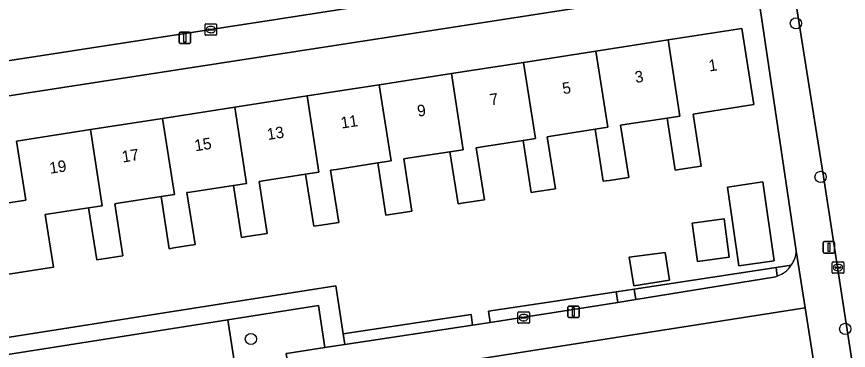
# Model space of a CAD drawing. Extents: x 160077 to 160948, y 386481 to 387498.
# Drawn here: x 160283.4 to 160355.9, y 387324.3 to 387353.4 of the extents above; entities that cross this region are included whole.
import ezdxf

# ---------------------------------------------------------------- set-up
doc = ezdxf.new("R2010")
doc.units = 0
for name, color, linetype in [('IMGEO_Boom', 7, 'Continuous'), ('IMGEO_Erf', 7, 'Continuous'), ('IMGEO_Groenvoorziening', 7, 'Continuous'), ('IMGEO_Haag', 7, 'Continuous'), ('IMGEO_Hek', 7, 'Continuous'), ('IMGEO_Kolk', 7, 'Continuous'), ('IMGEO_Lichtmast', 7, 'Continuous'), ('IMGEO_Pand', 7, 'Continuous'), ('IMGEO_Pand_nummerreeks', 7, 'Continuous'), ('IMGEO_Rijbaan_lokaal_open', 7, 'Continuous'), ('IMGEO_Voetpad_open', 7, 'Continuous')]:
    doc.layers.add(name, color=color, linetype=linetype)

msp = doc.modelspace()

# ---------------------------------------------------------------- linework, layer by layer
at = {"layer": 'IMGEO_Boom'}
for centre in [(160351.331, 387352.8), (160353.483, 387339.399), (160355.634, 387326.139), (160303.826, 387325.258)]:
    msp.add_circle(centre, 0.489, dxfattribs=at)
at = {"layer": 'IMGEO_Erf'}
for points in [[(160345.165, 387356.158), (160277.066, 387345.597)], [(160351.371, 387332.958), (160348.215, 387354.083)], [(160280.249, 387336.766), (160284.197, 387337.379), (160283.396, 387342.532), (160289.831, 387343.531), (160296.126, 387344.509), (160302.42, 387345.486), (160308.715, 387346.464), (160315.01, 387347.441), (160321.304, 387348.418), (160327.599, 387349.396), (160333.893, 387350.373), (160340.188, 387351.351), (160346.623, 387352.35), (160347.655, 387345.706), (160342.898, 387344.967), (160342.377, 387344.886), (160343.083, 387340.342), (160341.343, 387340.072), (160340.809, 387339.989), (160340.103, 387344.533), (160336.593, 387343.988), (160336.053, 387343.904), (160336.759, 387339.36), (160335.068, 387339.098), (160334.545, 387339.017), (160333.839, 387343.561), (160330.178, 387342.992), (160329.656, 387342.911), (160330.362, 387338.367), (160328.784, 387338.122), (160328.257, 387338.04), (160327.551, 387342.584), (160323.984, 387342.03), (160323.473, 387341.951), (160324.179, 387337.408), (160322.374, 387337.127), (160321.883, 387337.051), (160321.177, 387341.594), (160317.677, 387341.051), (160317.148, 387340.969), (160317.854, 387336.425), (160316.173, 387336.164), (160315.598, 387336.075), (160314.892, 387340.618), (160311.274, 387340.056), (160310.771, 387339.978), (160311.477, 387335.434), (160309.752, 387335.166), (160309.301, 387335.096), (160308.596, 387339.638), (160304.902, 387339.067), (160304.543, 387339.011), (160305.249, 387334.468), (160303.459, 387334.19), (160303.004, 387334.119), (160302.299, 387338.662), (160298.519, 387338.076), (160298.249, 387338.034), (160298.955, 387333.49), (160297.097, 387333.202), (160296.705, 387333.141), (160295.999, 387337.684), (160292.25, 387337.102), (160291.955, 387337.056), (160292.661, 387332.513), (160290.783, 387332.221), (160290.383, 387332.159), (160289.677, 387336.703), (160285.887, 387336.114), (160286.6, 387331.526), (160281.193, 387330.687)], [(160274.772, 387342.45), (160277.587, 387324.592), (160311.213, 387329.893), (160311.864, 387325.704), (160323.038, 387327.4), (160323.143, 387326.454), (160324.679, 387326.687), (160324.528, 387327.681), (160330.176, 387328.538), (160335.674, 387329.373), (160337.241, 387329.611), (160349.608, 387331.488), (160350.932, 387331.689)], [(160355.751, 387304.187), (160355.398, 387307.291), (160352.153, 387327.971), (160310.416, 387321.441), (160314.017, 387298.456), (160314.061, 387298.234), (160314.124, 387298.017), (160314.206, 387297.806), (160314.307, 387297.603), (160314.426, 387297.41), (160314.561, 387297.229), (160314.712, 387297.06), (160314.749, 387297.023), (160327.622, 387298.956), (160328.806, 387299.134), (160329.073, 387299.174), (160339.014, 387300.655), (160341.387, 387301.023), (160341.842, 387301.093), (160341.795, 387301.407), (160354.477, 387303.432)], [(160305.938, 387282.835), (160305.245, 387287.39), (160307.739, 387287.769), (160307.211, 387291.392), (160304.718, 387291.013), (160304.144, 387294.781), (160303.444, 387299.383), (160305.938, 387299.762), (160305.449, 387303.021), (160302.956, 387302.642), (160302.335, 387306.725), (160301.682, 387311.012), (160304.176, 387311.391), (160304.04, 387312.282), (160303.781, 387313.992), (160303.628, 387314.996), (160301.133, 387314.617), (160300.516, 387318.668), (160299.861, 387322.974), (160302.357, 387323.353), (160301.814, 387326.925), (160277.816, 387323.142), (160287.045, 387264.59)]]:
    msp.add_lwpolyline(points, dxfattribs=at)
for points in [[(160345.364, 387338.52), (160348.438, 387338.968), (160349.442, 387332.078), (160346.368, 387331.63)], [(160342.29, 387335.359), (160345.068, 387335.739), (160345.523, 387332.405), (160342.745, 387332.025)], [(160336.799, 387332.389), (160339.929, 387332.8), (160340.314, 387330.388), (160337.197, 387329.891)]]:
    msp.add_lwpolyline(points, close=True, dxfattribs=at)
msp.add_arc((160348.839, 387333.123), 2.537, 325.57268, 356.26205, dxfattribs=at)
at = {"layer": 'IMGEO_Groenvoorziening'}
for points in [[(160349.424, 387330.658), (160349.566, 387330.696), (160349.705, 387330.742), (160349.608, 387331.488), (160337.241, 387329.611), (160337.378, 387328.71)], [(160335.813, 387328.457), (160335.674, 387329.373), (160330.176, 387328.538), (160324.528, 387327.681), (160324.679, 387326.687)], [(160306.887, 387323.99), (160307.144, 387324.03), (160310.282, 387324.506), (160309.705, 387328.169), (160301.814, 387326.925), (160302.357, 387323.353), (160303.011, 387319.054), (160303.628, 387314.996), (160303.781, 387313.992), (160308.303, 387314.677), (160307.652, 387318.96)], [(160323.143, 387326.454), (160323.038, 387327.4), (160311.864, 387325.704), (160312.006, 387324.767)]]:
    msp.add_lwpolyline(points, close=True, dxfattribs=at)
msp.add_lwpolyline([(160350.932, 387331.689), (160349.608, 387331.488), (160349.705, 387330.742)], dxfattribs=at)
msp.add_arc((160348.846, 387333.123), 2.531, 289.83448, 325.48752, dxfattribs=at)
at = {"layer": 'IMGEO_Haag'}
for points in [[(160349.705, 387330.742), (160349.608, 387331.488), (160337.241, 387329.611), (160337.378, 387328.71), (160349.424, 387330.658), (160349.566, 387330.696)], [(160335.674, 387329.373), (160330.176, 387328.538), (160324.528, 387327.681), (160324.679, 387326.687), (160335.813, 387328.457)], [(160323.143, 387326.454), (160323.038, 387327.4), (160311.864, 387325.704), (160312.006, 387324.767)]]:
    msp.add_lwpolyline(points, close=True, dxfattribs=at)
at = {"layer": 'IMGEO_Hek'}
for points in [[(160337.241, 387329.611), (160349.608, 387331.488)], [(160330.176, 387328.538), (160335.674, 387329.373)], [(160311.864, 387325.704), (160323.038, 387327.4)]]:
    msp.add_lwpolyline(points, dxfattribs=at)
at = {"layer": 'IMGEO_Kolk'}
for p, q in [((160299.825, 387351.831), (160299.825, 387352.683)), ((160299.9, 387352.757), (160300.752, 387352.757)), ((160300.313, 387352.537), (160300.338, 387352.537)), ((160300.826, 387352.683), (160300.826, 387351.831)), ((160300.752, 387351.757), (160299.9, 387351.757)), ((160300.084, 387352.251), (160300.084, 387352.263)), ((160300.522, 387352.214), (160300.124, 387352.214)), ((160300.127, 387352.3), (160300.525, 387352.3)), ((160300.336, 387351.977), (160300.311, 387351.977)), ((160300.568, 387352.263), (160300.568, 387352.251)), ((160354.502, 387331.066), (160354.502, 387331.918)), ((160354.577, 387331.992), (160355.429, 387331.992)), ((160354.761, 387331.486), (160354.761, 387331.498)), ((160355.199, 387331.449), (160354.801, 387331.449)), ((160354.804, 387331.535), (160355.202, 387331.535)), ((160354.99, 387331.772), (160355.015, 387331.772)), ((160355.245, 387331.498), (160355.245, 387331.486)), ((160355.503, 387331.918), (160355.503, 387331.066)), ((160355.429, 387330.992), (160354.577, 387330.992)), ((160355.013, 387331.212), (160354.988, 387331.212)), ((160327.101, 387326.703), (160327.101, 387327.555)), ((160327.176, 387327.629), (160328.028, 387327.629)), ((160327.36, 387327.123), (160327.36, 387327.135)), ((160327.798, 387327.086), (160327.4, 387327.086)), ((160327.403, 387327.172), (160327.801, 387327.172)), ((160327.589, 387327.409), (160327.614, 387327.409)), ((160327.844, 387327.135), (160327.844, 387327.123)), ((160328.102, 387327.555), (160328.102, 387326.703)), ((160328.028, 387326.629), (160327.176, 387326.629)), ((160327.612, 387326.849), (160327.587, 387326.849))]:
    msp.add_line(p, q, dxfattribs=at)
for points in [[(160299.825, 387351.831), (160299.825, 387352.683)], [(160299.9, 387352.757), (160300.752, 387352.757)], [(160300.826, 387352.683), (160300.826, 387351.831)], [(160300.752, 387351.757), (160299.9, 387351.757)], [(160354.502, 387331.066), (160354.502, 387331.918)], [(160354.577, 387331.992), (160355.429, 387331.992)], [(160355.503, 387331.918), (160355.503, 387331.066)], [(160355.429, 387330.992), (160354.577, 387330.992)], [(160327.101, 387326.703), (160327.101, 387327.555)], [(160327.176, 387327.629), (160328.028, 387327.629)], [(160328.102, 387327.555), (160328.102, 387326.703)], [(160328.028, 387326.629), (160327.176, 387326.629)]]:
    msp.add_lwpolyline(points, dxfattribs=at)
for centre, radius, start, end in [((160299.902, 387352.681), 0.0765, 91.55205, 178.44795), ((160299.902, 387352.681), 0.0765, 91.55205, 178.44795), ((160300.75, 387352.681), 0.0765, 1.55205, 88.44795), ((160300.75, 387352.681), 0.0765, 1.55205, 88.44795), ((160299.902, 387351.833), 0.0765, 181.55205, 268.44795), ((160299.902, 387351.833), 0.0765, 181.55205, 268.44795), ((160300.124, 387352.26), 0.0403, 85.87752, 175.75265), ((160300.121, 387352.25), 0.0366, 178.93798, 274.71019), ((160300.525, 387352.257), 0.043, 264.86636, 352.45326), ((160300.529, 387352.262), 0.0386, 1.73085, 96.63898), ((160300.75, 387351.833), 0.0765, 271.55205, 358.44795), ((160300.75, 387351.833), 0.0765, 271.55205, 358.44795), ((160354.579, 387331.916), 0.0765, 91.55205, 178.44795), ((160354.579, 387331.916), 0.0765, 91.55205, 178.44795), ((160354.801, 387331.495), 0.0403, 85.87752, 175.75265), ((160354.798, 387331.485), 0.0366, 178.93798, 274.71019), ((160355.202, 387331.492), 0.043, 264.86636, 352.45326), ((160355.206, 387331.497), 0.0386, 1.73085, 96.63898), ((160355.427, 387331.916), 0.0765, 1.55205, 88.44795), ((160355.427, 387331.916), 0.0765, 1.55205, 88.44795), ((160354.579, 387331.068), 0.0765, 181.55205, 268.44795), ((160354.579, 387331.068), 0.0765, 181.55205, 268.44795), ((160355.427, 387331.068), 0.0765, 271.55205, 358.44795), ((160355.427, 387331.068), 0.0765, 271.55205, 358.44795), ((160327.178, 387327.553), 0.0765, 91.55205, 178.44795), ((160327.178, 387327.553), 0.0765, 91.55205, 178.44795), ((160327.4, 387327.132), 0.0403, 85.87752, 175.75265), ((160327.397, 387327.122), 0.0366, 178.93798, 274.71019), ((160327.801, 387327.129), 0.043, 264.86636, 352.45326), ((160327.805, 387327.134), 0.0386, 1.73085, 96.63898), ((160328.026, 387327.553), 0.0765, 1.55205, 88.44795), ((160328.026, 387327.553), 0.0765, 1.55205, 88.44795), ((160327.178, 387326.705), 0.0765, 181.55205, 268.44795), ((160327.178, 387326.705), 0.0765, 181.55205, 268.44795), ((160328.026, 387326.705), 0.0765, 271.55205, 358.44795), ((160328.026, 387326.705), 0.0765, 271.55205, 358.44795)]:
    msp.add_arc(centre, radius, start, end, dxfattribs=at)
for centre, major_axis, ratio, start_param, end_param in [((160300.312, 387352.257), (-0.387, 0.002), 0.722429, 4.712389, 7.853982), ((160300.337, 387352.257), (-0.39, 0.002), 0.717154, 1.570796, 4.712389), ((160354.989, 387331.492), (-0.387, 0.002), 0.722429, 4.712389, 7.853982), ((160355.014, 387331.492), (-0.39, 0.002), 0.717154, 1.570796, 4.712389), ((160327.588, 387327.129), (-0.387, 0.002), 0.722429, 4.712389, 7.853982), ((160327.613, 387327.129), (-0.39, 0.002), 0.717154, 1.570796, 4.712389)]:
    msp.add_ellipse(centre, major_axis=major_axis, ratio=ratio, start_param=start_param, end_param=end_param, dxfattribs=at)
at = {"layer": 'IMGEO_Lichtmast'}
for p, q in [((160297.568, 387351.133), (160297.568, 387351.933)), ((160297.568, 387351.933), (160297.568, 387351.133)), ((160297.668, 387352.033), (160298.458, 387352.033)), ((160298.458, 387352.033), (160297.668, 387352.033)), ((160298.558, 387351.933), (160298.558, 387351.133)), ((160298.558, 387351.133), (160298.558, 387351.933)), ((160298.458, 387351.033), (160297.668, 387351.033)), ((160297.668, 387351.033), (160298.458, 387351.033)), ((160353.713, 387332.86), (160353.713, 387333.66)), ((160353.713, 387333.66), (160353.713, 387332.86)), ((160353.813, 387333.76), (160354.603, 387333.76)), ((160354.603, 387333.76), (160353.813, 387333.76)), ((160354.703, 387333.66), (160354.703, 387332.86)), ((160354.703, 387332.86), (160354.703, 387333.66)), ((160354.603, 387332.76), (160353.813, 387332.76)), ((160353.813, 387332.76), (160354.603, 387332.76)), ((160331.448, 387327.224), (160331.448, 387328.024)), ((160331.448, 387328.024), (160331.448, 387327.224)), ((160331.548, 387328.124), (160332.338, 387328.124)), ((160332.338, 387328.124), (160331.548, 387328.124)), ((160332.438, 387328.024), (160332.438, 387327.224)), ((160332.438, 387327.224), (160332.438, 387328.024)), ((160332.338, 387327.124), (160331.548, 387327.124)), ((160331.548, 387327.124), (160332.338, 387327.124))]:
    msp.add_line(p, q, dxfattribs=at)
for points in [[(160297.988, 387351.908), (160298.138, 387351.908), (160298.138, 387351.158), (160297.988, 387351.158), (160297.988, 387351.908)], [(160354.133, 387333.635), (160354.283, 387333.635), (160354.283, 387332.885), (160354.133, 387332.885), (160354.133, 387333.635)], [(160331.868, 387327.999), (160332.018, 387327.999), (160332.018, 387327.249), (160331.868, 387327.249), (160331.868, 387327.999)]]:
    msp.add_lwpolyline(points, dxfattribs=at)
for centre, start, end in [((160297.668, 387351.933), 90, 180), ((160297.668, 387351.933), 90, 180), ((160298.458, 387351.933), 0, 90), ((160298.458, 387351.933), 360, 90), ((160297.668, 387351.133), 180, 270), ((160297.668, 387351.133), 180, 270), ((160298.458, 387351.133), 270, 0), ((160298.458, 387351.133), 270, 0), ((160353.813, 387333.66), 90, 180), ((160353.813, 387333.66), 90, 180), ((160354.603, 387333.66), 0, 90), ((160354.603, 387333.66), 360, 90), ((160353.813, 387332.86), 180, 270), ((160353.813, 387332.86), 180, 270), ((160354.603, 387332.86), 270, 0), ((160354.603, 387332.86), 270, 0), ((160331.548, 387328.024), 90, 180), ((160331.548, 387328.024), 90, 180), ((160332.338, 387328.024), 0, 90), ((160332.338, 387328.024), 360, 90), ((160331.548, 387327.224), 180, 270), ((160331.548, 387327.224), 180, 270), ((160332.338, 387327.224), 270, 0), ((160332.338, 387327.224), 270, 0)]:
    msp.add_arc(centre, 0.1, start, end, dxfattribs=at)
at = {"layer": 'IMGEO_Pand'}
for points in [[(160346.623, 387352.35), (160340.188, 387351.351), (160341.22, 387344.705), (160340.103, 387344.533), (160340.809, 387339.989), (160341.343, 387340.072), (160343.083, 387340.342), (160342.377, 387344.886), (160342.898, 387344.967), (160347.655, 387345.706)], [(160340.188, 387351.351), (160333.893, 387350.373), (160334.925, 387343.727), (160333.839, 387343.561), (160334.545, 387339.017), (160335.068, 387339.098), (160336.759, 387339.36), (160336.053, 387343.904), (160336.593, 387343.988), (160340.103, 387344.533), (160341.22, 387344.705)], [(160333.893, 387350.373), (160327.599, 387349.396), (160328.631, 387342.75), (160327.551, 387342.584), (160328.257, 387338.04), (160328.784, 387338.122), (160330.362, 387338.367), (160329.656, 387342.911), (160330.178, 387342.992), (160333.839, 387343.561), (160334.925, 387343.727)], [(160327.599, 387349.396), (160321.304, 387348.418), (160322.336, 387341.772), (160321.177, 387341.594), (160321.883, 387337.051), (160322.374, 387337.127), (160324.179, 387337.408), (160323.473, 387341.951), (160323.984, 387342.03), (160327.551, 387342.584), (160328.631, 387342.75)], [(160321.304, 387348.418), (160315.01, 387347.441), (160316.042, 387340.795), (160314.892, 387340.618), (160315.598, 387336.075), (160316.173, 387336.164), (160317.854, 387336.425), (160317.148, 387340.969), (160317.677, 387341.051), (160321.177, 387341.594), (160322.336, 387341.772)], [(160315.01, 387347.441), (160308.715, 387346.464), (160309.747, 387339.817), (160308.596, 387339.638), (160309.301, 387335.096), (160309.752, 387335.166), (160311.477, 387335.434), (160310.771, 387339.978), (160311.274, 387340.056), (160314.892, 387340.618), (160316.042, 387340.795)], [(160308.715, 387346.464), (160302.42, 387345.486), (160303.452, 387338.839), (160302.299, 387338.662), (160303.004, 387334.119), (160303.459, 387334.19), (160305.249, 387334.468), (160304.543, 387339.011), (160304.902, 387339.067), (160308.596, 387339.638), (160309.747, 387339.817)], [(160302.42, 387345.486), (160296.126, 387344.509), (160297.158, 387337.865), (160295.999, 387337.684), (160296.705, 387333.141), (160297.097, 387333.202), (160298.955, 387333.49), (160298.249, 387338.034), (160298.519, 387338.076), (160302.299, 387338.662), (160303.452, 387338.839)], [(160296.126, 387344.509), (160289.831, 387343.531), (160290.862, 387336.887), (160289.677, 387336.703), (160290.383, 387332.159), (160290.783, 387332.221), (160292.661, 387332.513), (160291.955, 387337.056), (160292.25, 387337.102), (160295.999, 387337.684), (160297.158, 387337.865)], [(160289.831, 387343.531), (160283.396, 387342.532), (160284.197, 387337.379), (160280.249, 387336.766), (160281.193, 387330.687), (160286.6, 387331.526), (160285.887, 387336.114), (160289.677, 387336.703), (160290.862, 387336.887)], [(160349.442, 387332.078), (160348.438, 387338.968), (160345.364, 387338.52), (160346.368, 387331.63)], [(160342.29, 387335.359), (160342.745, 387332.025), (160345.523, 387332.405), (160345.068, 387335.739)], [(160336.799, 387332.389), (160337.197, 387329.891), (160340.314, 387330.388), (160339.929, 387332.8)]]:
    msp.add_lwpolyline(points, close=True, dxfattribs=at)
at = {"layer": 'IMGEO_Rijbaan_lokaal_open'}
for points in [[(160371.986, 387266.851), (160369.216, 387284.504), (160369.173, 387285.284), (160366.562, 387302.662), (160358.665, 387353.61), (160352.799, 387391.033), (160352.774, 387391.05), (160350.809, 387403.731), (160343.75, 387402.638), (160348.577, 387372.565), (160348.617, 387372.556), (160351.293, 387354.598), (160351.403, 387354.063), (160353.156, 387343.079), (160353.738, 387339.43), (160357.73, 387313.614), (160358.294, 387309.971), (160362.387, 387284.057), (160362.946, 387280.357), (160363.189, 387278.751), (160367.156, 387253.21)], [(160306.164, 387353.162), (160324.17, 387355.972), (160323.094, 387362.939), (160304.367, 387360.049), (160262.397, 387353.48), (160265.535, 387333.801), (160272.364, 387334.875), (160271.331, 387341.446)], [(160276.556, 387348.583), (160306.164, 387353.162)]]:
    msp.add_lwpolyline(points, dxfattribs=at)
at = {"layer": 'IMGEO_Voetpad_open'}
for points in [[(160344.432, 387359.134), (160326.936, 387356.404), (160324.17, 387355.972), (160306.164, 387353.162), (160276.556, 387348.583)], [(160347.434, 387358.849), (160348.215, 387354.083), (160351.371, 387332.958), (160352.153, 387327.971), (160355.398, 387307.291), (160355.751, 387304.187), (160356.842, 387299.449), (160360.174, 387278.766), (160360.463, 387276.972), (160360.469, 387276.973), (160361.388, 387270.942), (160364.673, 387250.186), (160364.703, 387250), (160364.966, 387248.339), (160365.847, 387243.204)], [(160277.066, 387345.597), (160345.165, 387356.158)], [(160358.294, 387309.971), (160357.572, 387309.856), (160356.995, 387313.497), (160357.73, 387313.614), (160353.738, 387339.43), (160353.156, 387343.079), (160351.403, 387354.063), (160351.293, 387354.598)], [(160310.416, 387321.441), (160352.153, 387327.971), (160351.371, 387332.958)], [(160349.705, 387330.742), (160349.566, 387330.696), (160349.424, 387330.658), (160337.378, 387328.71), (160335.813, 387328.457), (160324.679, 387326.687), (160323.143, 387326.454), (160312.006, 387324.767), (160310.282, 387324.506), (160307.144, 387324.03), (160306.887, 387323.99), (160307.652, 387318.96), (160308.303, 387314.677), (160308.563, 387312.97), (160310.106, 387302.817), (160310.355, 387301.177), (160312.04, 387291.582), (160312.395, 387289.271), (160314.048, 387278.741), (160314.268, 387277.238)]]:
    msp.add_lwpolyline(points, dxfattribs=at)
for points in [[(160301.814, 387326.925), (160309.705, 387328.169), (160310.282, 387324.506), (160312.006, 387324.767), (160311.864, 387325.704), (160311.213, 387329.893), (160277.587, 387324.592), (160277.816, 387323.142)], [(160337.241, 387329.611), (160335.674, 387329.373), (160335.813, 387328.457), (160337.378, 387328.71)]]:
    msp.add_lwpolyline(points, close=True, dxfattribs=at)
for centre, radius, start, end in [((160348.839, 387333.123), 2.537, 325.57268, 356.26205), ((160348.846, 387333.123), 2.531, 289.83448, 325.48752)]:
    msp.add_arc(centre, radius, start, end, dxfattribs=at)

# ---------------------------------------------------------------- texts
at = {"layer": 'IMGEO_Pand_nummerreeks'}
for s, p in [('1', (160343.805, 387348.593)), ('3', (160337.37, 387347.595)), ('5', (160331.047, 387346.613)), ('7', (160324.725, 387345.631)), ('9', (160318.402, 387344.649)), ('11', (160311.737, 387343.613)), ('13', (160305.301, 387342.615)), ('15', (160298.979, 387341.633)), ('17', (160292.656, 387340.651)), ('19', (160286.333, 387339.669))]:
    msp.add_text(s, height=1, rotation=8.82928, dxfattribs=at).set_placement(p)

doc.saveas('drawing.dxf')
